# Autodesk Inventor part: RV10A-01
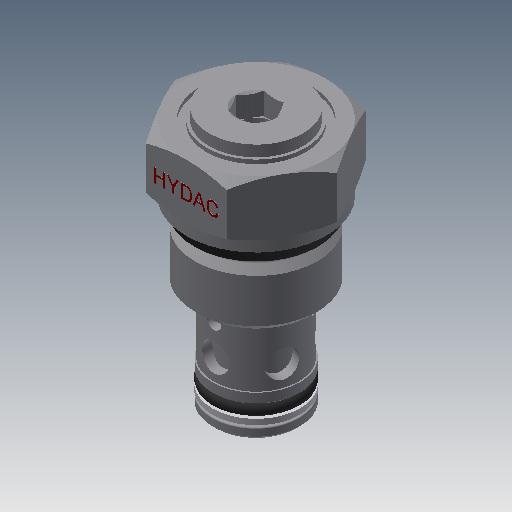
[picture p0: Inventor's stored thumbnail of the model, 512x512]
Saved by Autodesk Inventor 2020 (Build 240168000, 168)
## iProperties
DataBaseUnit: MM
Created: 2014-06
Part Number: RV10A-01
Material: Generico
Document SubType Name: Modeling
Designer: Carlo
Density: 1 g/cm^3
Appearance: Default
Author: Carlo
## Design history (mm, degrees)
node "SW3DPS-10000281768-SWB-000_01-STANDARD.sat1"
node "Piano di lavoro1"
node "Piano di lavoro2"
node "Asse di lavoro1"
node "Solido1"
node "Base1"
other parameters: "d0" = 0, "d1" = 0
